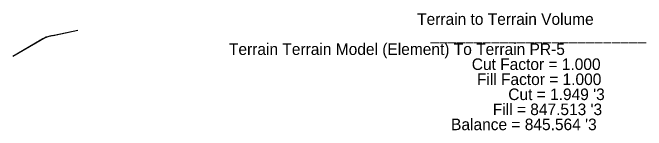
# Model space of a CAD drawing. Extents: x 998140 to 998796, y 1983717 to 1983839.
import ezdxf

# ---------------------------------------------------------------- set-up
doc = ezdxf.new("R2010")
doc.units = 0
doc.layers.add('Default', color=7, linetype='Continuous')
doc.layers.add('MOD_Edge of Pavement', color=7, linetype='Continuous')

msp = doc.modelspace()

# ---------------------------------------------------------------- linework, layer by layer
at = {"layer": 'Default'}
for p, q in [((998174.07, 1983814.23), (998207.01, 1983821.36)), ((998139.54, 1983794.46), (998174.07, 1983814.23))]:
    msp.add_line(p, q, dxfattribs=at)
msp.add_arc((998192.21, 1983767), 50, 102.22292, 119.79218, dxfattribs=at)
at = {"layer": 'MOD_Edge of Pavement'}
for p, q in [((998181.62, 1983815.86), (998207.01, 1983821.36)), ((998139.54, 1983794.46), (998167.36, 1983810.39))]:
    msp.add_line(p, q, dxfattribs=at)
msp.add_arc((998192.21, 1983767), 50, 102.22292, 119.79218, dxfattribs=at)

# ---------------------------------------------------------------- texts
at = {"layer": 'Default'}
for s, p in [('Terrain to Terrain Volume', (998558.33, 1983826.78)), ('Terrain Terrain Model (Element) To Terrain PR-5', (998363.51, 1983795.58)), ('_________________________', (998572.35, 1983811.18)), ('Cut Factor = 1.000', (998614.93, 1983779.98)), ('Fill Factor = 1.000', (998620.21, 1983764.38)), ("Cut = 1.949 '3", (998652.69, 1983748.78)), ("Fill = 847.513 '3", (998636.66, 1983733.18)), ("Balance = 845.564 '3", (998593.49, 1983717.58))]:
    msp.add_text(s, height=12, dxfattribs=at).set_placement(p)

doc.saveas('drawing.dxf')
